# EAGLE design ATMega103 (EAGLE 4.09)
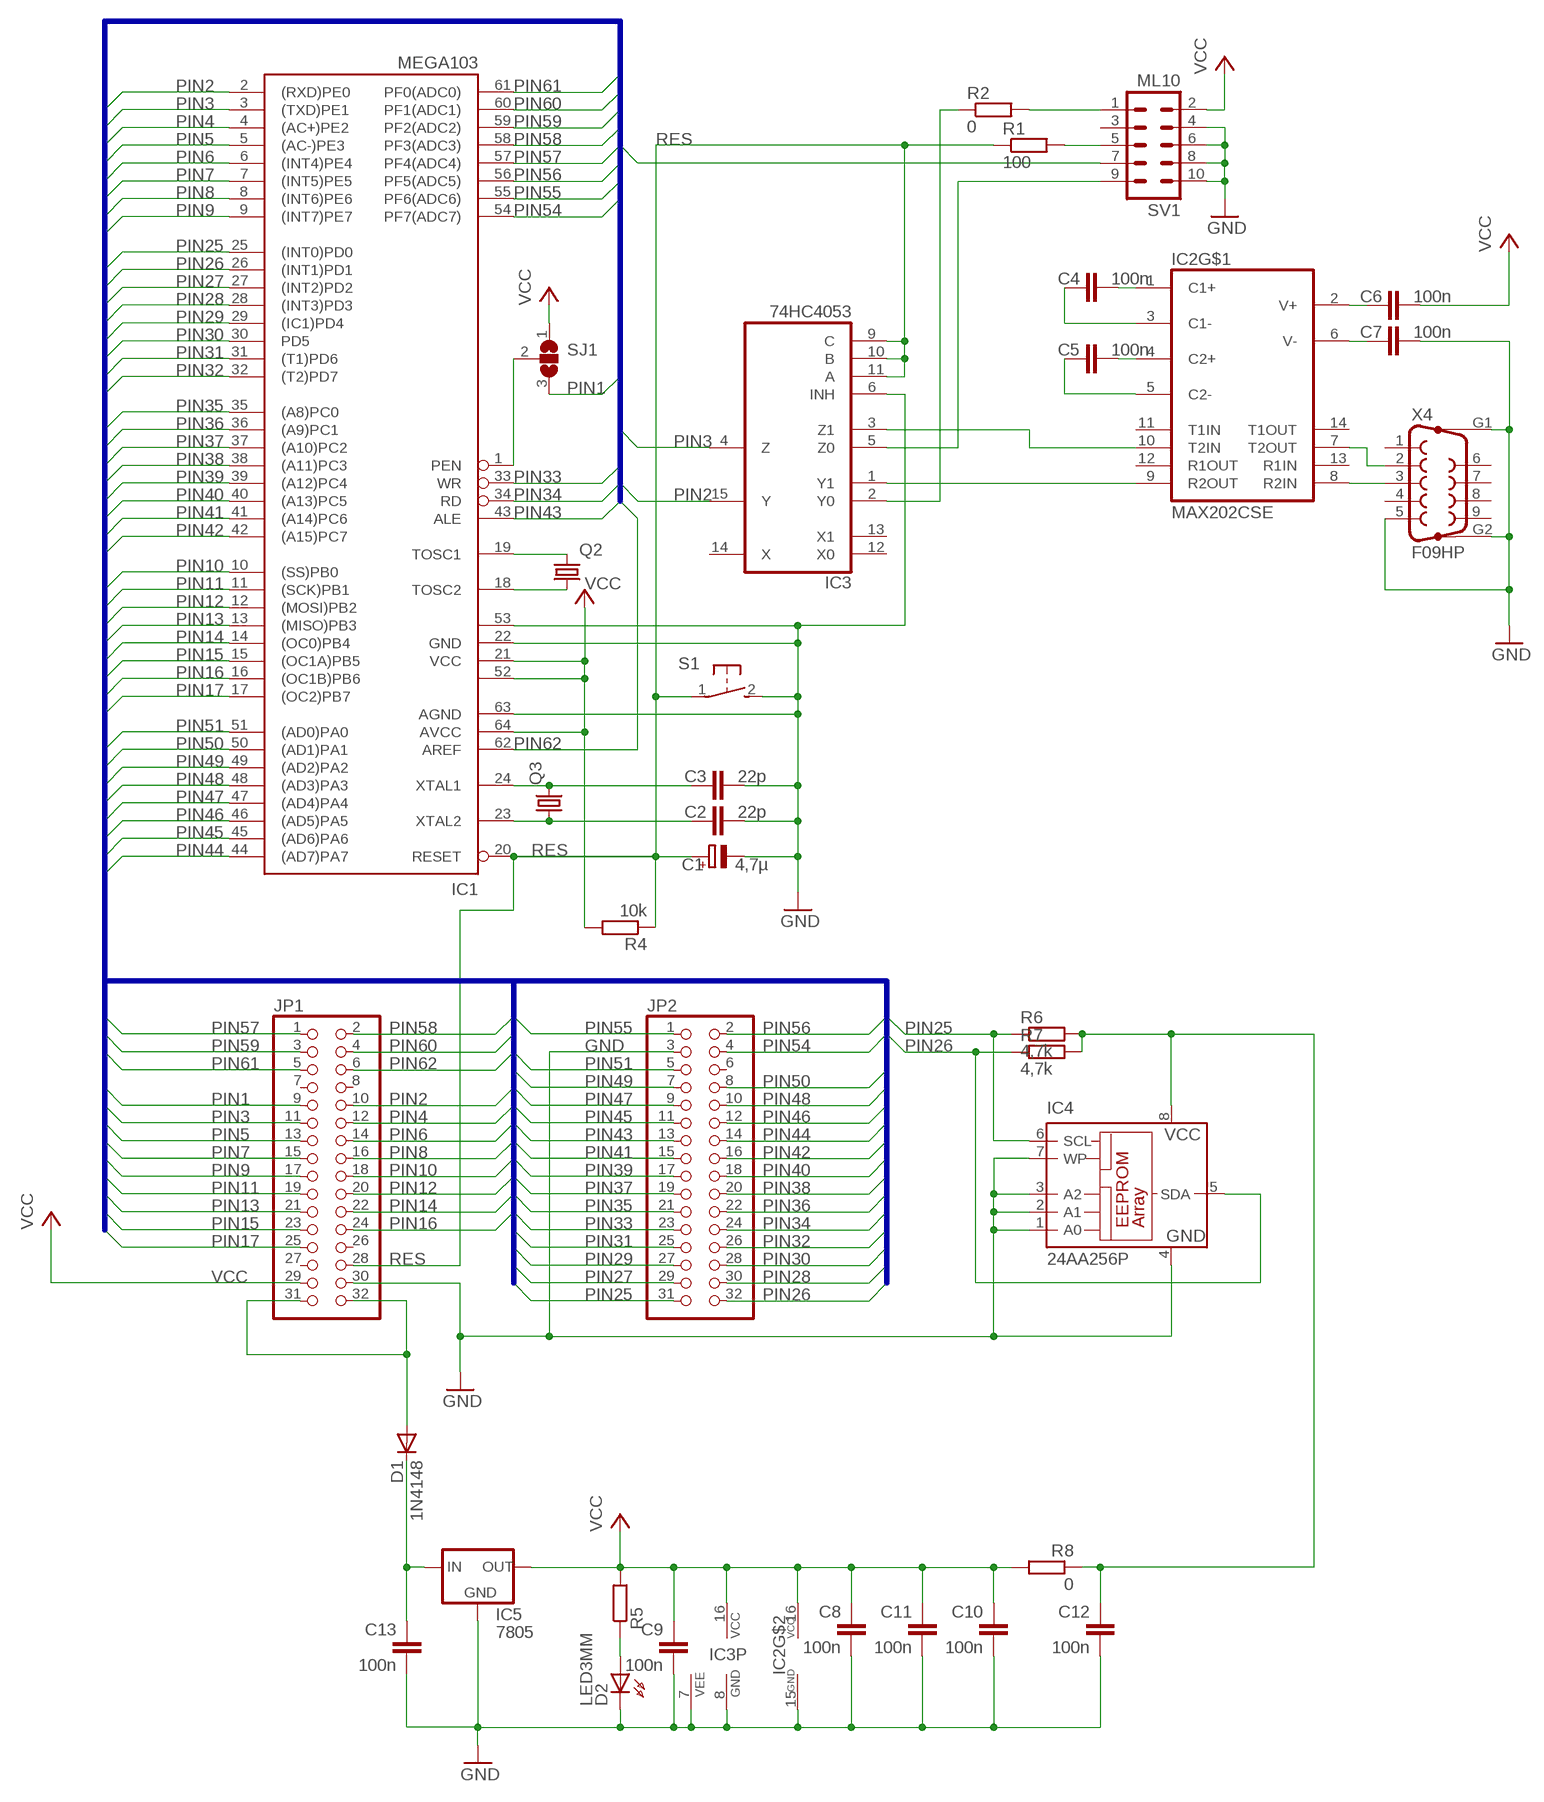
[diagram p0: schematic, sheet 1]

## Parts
C1  4,7µ  CPOL-EUE2-5  [E2-5]
C2  22p  C-EUC3216  [C3216]
C3  22p  C-EUC3216  [C3216]
C4  100n  C-EUC3216  [C3216]
C5  100n  C-EUC3216  [C3216]
C6  100n  C-EUC3216  [C3216]
C7  100n  C-EUC3216  [C3216]
C8  100n  C-EUC3216  [C3216]
C9  100n  C-EUC3216  [C3216]
C10  100n  C-EUC3216  [C3216]
C11  100n  C-EUC3216  [C3216]
C12  100n  C-EUC1206  [C1206]
C13  100n  C-EUC1206  [C1206]
D1  1N4148  DIODE-SOD106-R  [SOD106-R]
D2  LED3MM  [LED3MM]
IC1  MEGA103  [TQFP64]
IC2  MAX202CSE  [SO16]
IC3  74HC4053  4053D  [SO16]
IC4  24AA256P  [DIL8]
IC5  7805  78XXL  [78XXL]
JP1  PINHD-2X16  [2X16]
JP2  PINHD-2X16  [2X16]
Q2  TC26H  [TC26H]
Q3  HC49/S  [HC49/S]
R1  100  R-EU_R3216  [R3216]
R2  0  R-EU_R3216  [R3216]
R4  10k  R-EU_R3216  [R3216]
R5  R-EU_R3216  [R3216]
R6  4,7k  R-EU_M3216  [M3216]
R7  4,7k  R-EU_M3216  [M3216]
R8  0  R-EU_R3216  [R3216]
S1  31-XX  [B3F-31XX]
SJ1  SJ2W  [SJ_2]
SV1  ML10  [ML10]
X4  F09HP  [F09HP]

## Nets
GND: C1.- C2.2 C3.2 C7.2 C8.2 C9.2 C10.2 C11.2 C12.2 C13.2 D2.K(C) IC1.22(GND) IC1.53(GND1) IC1.63(AGND) IC2.15(GND) IC3.6(INH) IC3.7(VEE) IC3.8(GND) IC4.1(A0) IC4.2(A1) IC4.3(A2) IC4.4(GND) IC4.7(WP) IC5.GND JP1.30 JP2.3 S1.2(S) SV1.4 SV1.6 SV1.8 SV1.10 X4.5 X4.G1 X4.G2
N$1: C3.1 IC1.24(XTAL1) Q3.2
N$2: C2.1 IC1.23(XTAL2) Q3.1
N$3: IC1.19(TOSC1) Q2.1
N$4: IC1.18(TOSC2) Q2.2
N$9: D2.A R5.1
N$10: R2.2 SV1.1
N$11: D1.A JP1.31 JP1.32
N$12: IC1.1(PEN) SJ1.2
N$13: C12.1 IC4.8(VCC) R6.2 R7.2 R8.1
N$14: IC2.9(R2OUT) IC3.1(Y1)
N$16: IC3.5(Z0) SV1.9
N$17: IC3.2(Y0) R2.1
N$18: IC2.10(T2IN) IC3.3(Z1)
N$19: C4.2 IC2.1(C1+)
N$20: C5.2 IC2.4(C2+)
N$21: C5.1 IC2.5(C2-)
N$22: C6.1 IC2.2(V+)
N$23: C7.1 IC2.6(V-)
N$24: IC2.7(T2OUT) X4.2
N$25: IC2.8(R2IN) X4.3
N$26: C13.1 D1.C IC5.IN
N$28: R1.2 SV1.5
N$29: C4.1 IC2.3(C1-)
PIN1: JP1.9 SJ1.3
PIN2: IC1.2((RXD)PE0) IC3.15(Y) JP1.10
PIN3: IC1.3((TXD)PE1) IC3.4(Z) JP1.11
PIN4: IC1.4((AC+)PE2) JP1.12
PIN5: IC1.5((AC-)PE3) JP1.13
PIN6: IC1.6((INT4)PE4) JP1.14
PIN7: IC1.7((INT5)PE5) JP1.15
PIN8: IC1.8((INT6)PE6) JP1.16
PIN9: IC1.9((INT7)PE7) JP1.17
PIN10: IC1.10((SS)PB0) JP1.18
PIN11: IC1.11((SCK)PB1) JP1.19 SV1.7
PIN12: IC1.12((MOSI)PB2) JP1.20
PIN13: IC1.13((MISO)PB3) JP1.21
PIN14: IC1.14((OC0)PB4) JP1.22
PIN15: IC1.15((OC1A)PB5) JP1.23
PIN16: IC1.16((OC1B)PB6) JP1.24
PIN17: IC1.17((OC2)PB7) JP1.25
PIN25: IC1.25((INT0)PD0) IC4.6(SCL) JP2.31 R6.1
PIN26: IC1.26((INT1)PD1) IC4.5(SDA) JP2.32 R7.1
PIN27: IC1.27((INT2)PD2) JP2.29
PIN28: IC1.28((INT3)PD3) JP2.30
PIN29: IC1.29((IC1)PD4) JP2.27
PIN30: IC1.30(PD5) JP2.28
PIN31: IC1.31((T1)PD6) JP2.25
PIN32: IC1.32((T2)PD7) JP2.26
PIN33: IC1.33(WR) JP2.23
PIN34: IC1.34(RD) JP2.24
PIN35: IC1.35((A8)PC0) JP2.21
PIN36: IC1.36((A9)PC1) JP2.22
PIN37: IC1.37((A10)PC2) JP2.19
PIN38: IC1.38((A11)PC3) JP2.20
PIN39: IC1.39((A12)PC4) JP2.17
PIN40: IC1.40((A13)PC5) JP2.18
PIN41: IC1.41((A14)PC6) JP2.15
PIN42: IC1.42((A15)PC7) JP2.16
PIN43: IC1.43(ALE) JP2.13
PIN44: IC1.44((AD7)PA7) JP2.14
PIN45: IC1.45((AD6)PA6) JP2.11
PIN46: IC1.46((AD5)PA5) JP2.12
PIN47: IC1.47((AD4)PA4) JP2.9
PIN48: IC1.48((AD3)PA3) JP2.10
PIN49: IC1.49((AD2)PA2) JP2.7
PIN50: IC1.50((AD1)PA1) JP2.8
PIN51: IC1.51((AD0)PA0) JP2.5
PIN54: IC1.54(PF7(ADC7)) JP2.4
PIN55: IC1.55(PF6(ADC6)) JP2.1
PIN56: IC1.56(PF5(ADC5)) JP2.2
PIN57: IC1.57(PF4(ADC4)) JP1.1
PIN58: IC1.58(PF3(ADC3)) JP1.2
PIN59: IC1.59(PF2(ADC2)) JP1.3
PIN60: IC1.60(PF1(ADC1)) JP1.4
PIN61: IC1.61(PF0(ADC0)) JP1.5
PIN62: IC1.62(AREF) JP1.6
RES: C1.+ IC1.20(RESET) IC3.9(C) IC3.10(B) IC3.11(A) JP1.28 R1.1 R4.1 S1.1(P)
VCC: C6.2 C8.1 C9.1 C10.1 C11.1 IC1.21(VCC) IC1.52(VCC1) IC1.64(AVCC) IC2.16(VCC) IC3.16(VCC) IC5.OUT JP1.29 R4.2 R5.2 R8.2 SJ1.1 SV1.2
Unconnected: IC2.11(T1IN) IC2.12(R1OUT) IC2.13(R1IN) IC2.14(T1OUT) IC3.12(X0) IC3.13(X1) IC3.14(X) JP1.7 JP1.8 JP1.26 JP1.27 JP2.6 SV1.3 X4.1 X4.4 X4.6 X4.7 X4.8 X4.9

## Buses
PIN[1..64]

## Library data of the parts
C1 = rcl:CPOL-EU: POLARIZED CAPACITOR, European symbol
C2-C13 = rcl:C-EU: CAPACITOR, European symbol
D1 = diode:DIODE-: DIODE
D2 = led:LED3MM: LED
IC1 = atmel:MEGA103*: MICROCONTROLLER Low-voltage (L) 128 Kbytes FLASH 4 Kbytes SRAM 2 Kbytes EEPROM UART RTC 8-channel 10 bit ADC
IC2 = maxim:MAX202CSE
IC3 = 40xx:4053: Triple 2-channel ANALOG MULTIPLEXER
IC4 = microchip:24*: Serial EEPROM I2C
IC5 = v-reg:78XXL: VOLTAGE REGULATOR
JP1 JP2 = pinhead:PINHD-2X16: PIN HEADER
Q2 = crystal:TC26H: CRYSTAL
Q3 = crystal:HC49/S: CRYSTAL
R1 R2 R4-R8 = rcl:R-EU_: RESISTOR, European symbol
S1 = switch-omron:31-XX: OMRON SWITCH
SJ1 = jumper:SJ2W: SMD solder JUMPER
SV1 = CON-ML:ML10
X4 = SUBD-A:F09HP

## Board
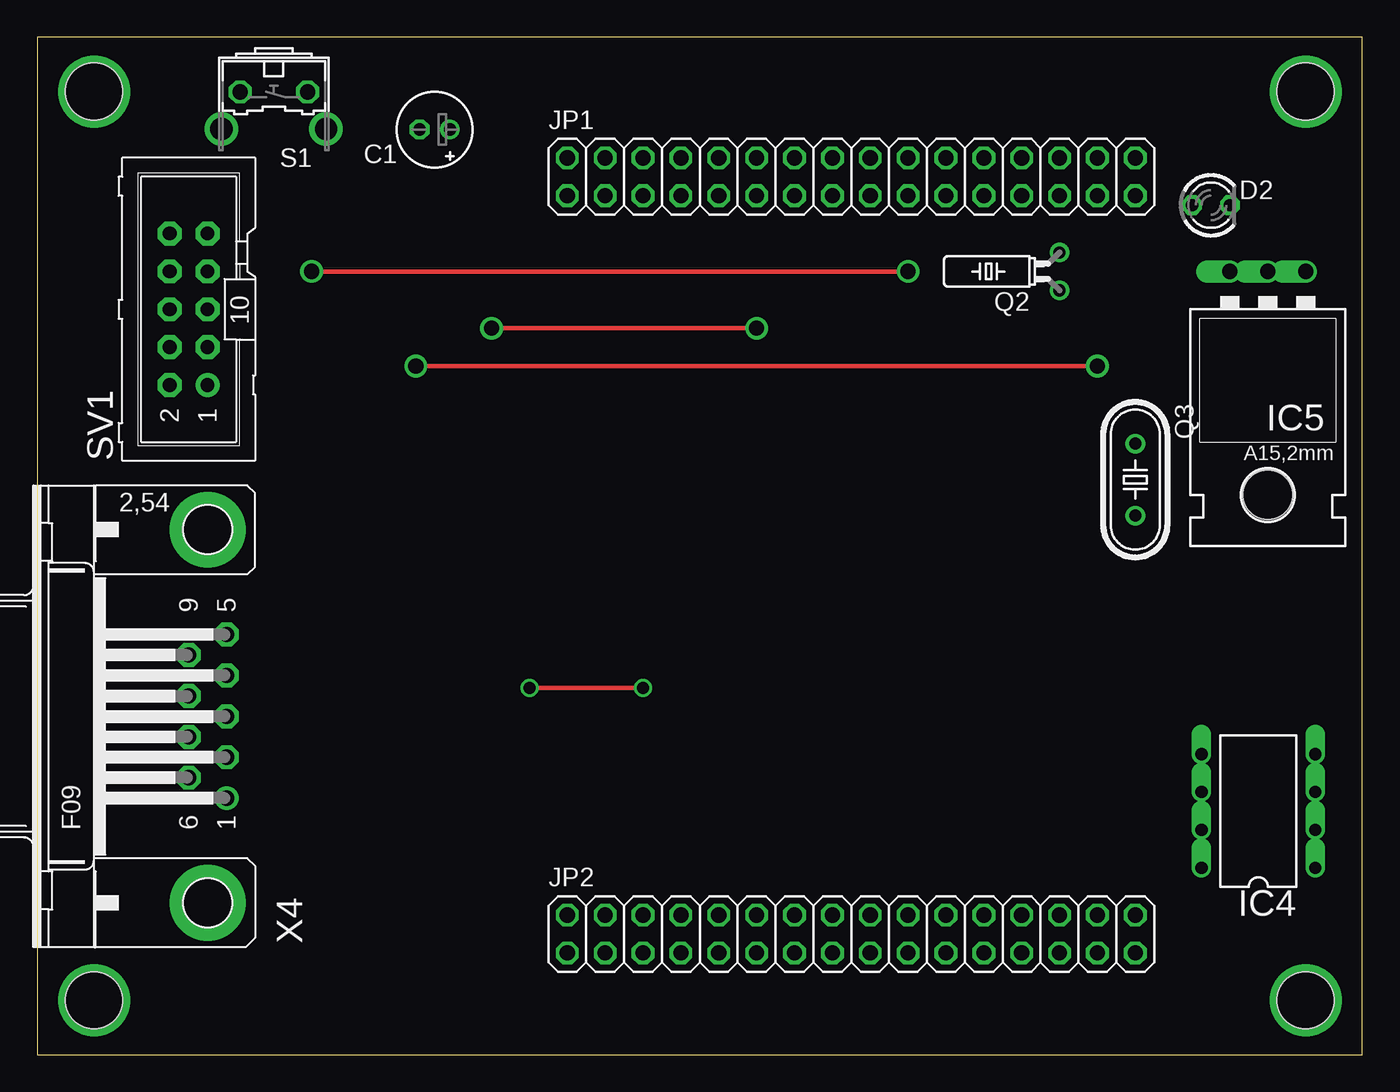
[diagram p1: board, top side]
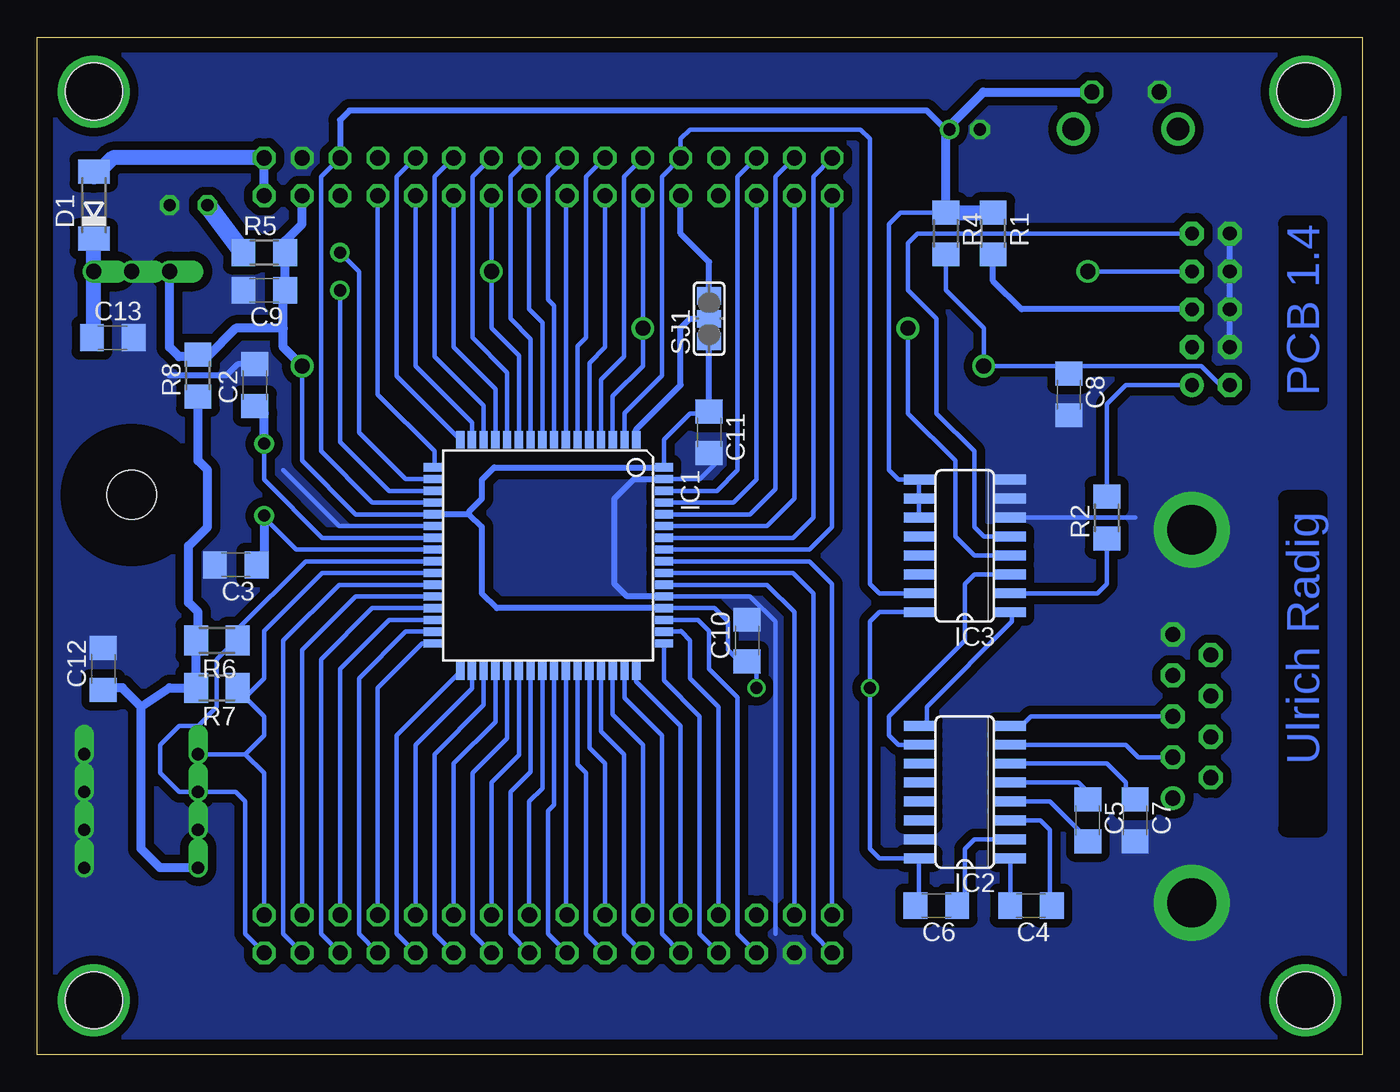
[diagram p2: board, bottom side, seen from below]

Size 88.88 x 68.25 mm. Coordinates in mm from the lower left corner, seen from the top.
Outline: 0,0 88.88,0 88.88,68.25 0,68.25 0,0
Copper layers used: Top, Bottom
Holes 3.81 mm at 3.8,64.6 3.8,3.64 85.08,3.64 85.08,64.6

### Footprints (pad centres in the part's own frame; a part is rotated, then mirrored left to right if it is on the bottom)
E2-5 = drill 0.813 pad 1.27 round: + -1.016,0 | drill 0.813 pad 1.27 octagon: - 1.016,0
C3216 = smd 1.6 x 1.8: 1 -1.4,0; 2 1.4,0
C1206 = smd 1.6 x 1.8: 1 -1.4,0; 2 1.4,0
SOD106-R = smd 1.6 x 2.1: A 2.25,0; C -2.25,0
LED3MM = drill 0.813 octagon: A -1.27,0; K 1.27,0
TQFP64 = smd 1.194 x 0.559: 1 -7.76,5.905; 2 -7.76,5.118; 3 -7.76,4.331; 4 -7.76,3.543; 5 -7.76,2.756; 6 -7.76,1.968; 7 -7.76,1.181; 8 -7.76,0.394; 9 -7.76,-0.394; 10 -7.76,-1.181; 11 -7.76,-1.968; 12 -7.76,-2.756; 13 -7.76,-3.543; 14 -7.76,-4.331; 15 -7.76,-5.118; 16 -7.76,-5.905; 33 7.76,-5.905; 34 7.76,-5.118; 35 7.76,-4.331; 36 7.76,-3.543; 37 7.76,-2.756; 38 7.76,-1.968; 39 7.76,-1.181; 40 7.76,-0.394; 41 7.76,0.394; 42 7.76,1.181; 43 7.76,1.968; 44 7.76,2.756; 45 7.76,3.543; 46 7.76,4.331; 47 7.76,5.118; 48 7.76,5.905 | smd 0.559 x 1.194: 17 -5.905,-7.76; 18 -5.118,-7.76; 19 -4.331,-7.76; 20 -3.543,-7.76; 21 -2.756,-7.76; 22 -1.968,-7.76; 23 -1.181,-7.76; 24 -0.394,-7.76; 25 0.394,-7.76; 26 1.181,-7.76; 27 1.968,-7.76; 28 2.756,-7.76; 29 3.543,-7.76; 30 4.331,-7.76; 31 5.118,-7.76; 32 5.905,-7.76; 49 5.905,7.76; 50 5.118,7.76; 51 4.331,7.76; 52 3.543,7.76; 53 2.756,7.76; 54 1.968,7.76; 55 1.181,7.76; 56 0.394,7.76; 57 -0.394,7.76; 58 -1.181,7.76; 59 -1.968,7.76; 60 -2.756,7.76; 61 -3.543,7.76; 62 -4.331,7.76; 63 -5.118,7.76; 64 -5.905,7.76
SO16 = smd 0.66 x 2.032: 1 -4.445,-3.073; 2 -3.175,-3.073; 3 -1.905,-3.073; 4 -0.635,-3.073; 5 0.635,-3.073; 6 1.905,-3.073; 7 3.175,-3.073; 8 4.445,-3.073; 9 4.445,3.073; 10 3.175,3.073; 11 1.905,3.073; 12 0.635,3.073; 13 -0.635,3.073; 14 -1.905,3.073; 15 -3.175,3.073; 16 -4.445,3.073
DIL8 = drill 0.813 offset: 1 -3.81,-3.81; 2 -1.27,-3.81; 3 1.27,-3.81; 4 3.81,-3.81; 5 3.81,3.81; 6 1.27,3.81; 7 -1.27,3.81; 8 -3.81,3.81
78XXL = drill 1.016 offset: GND 0,-3.81; IN -2.54,-3.81; OUT 2.54,-3.81 | hole 3.302: 0,11.176
2X16 = drill 1.016 octagon: 1 -19.05,-1.27; 2 -19.05,1.27; 3 -16.51,-1.27; 4 -16.51,1.27; 5 -13.97,-1.27; 6 -13.97,1.27; 7 -11.43,-1.27; 8 -11.43,1.27; 9 -8.89,-1.27; 10 -8.89,1.27; 11 -6.35,-1.27; 12 -6.35,1.27; 13 -3.81,-1.27; 14 -3.81,1.27; 15 -1.27,-1.27; 16 -1.27,1.27; 17 1.27,-1.27; 18 1.27,1.27; 19 3.81,-1.27; 20 3.81,1.27; 21 6.35,-1.27; 22 6.35,1.27; 23 8.89,-1.27; 24 8.89,1.27; 25 11.43,-1.27; 26 11.43,1.27; 27 13.97,-1.27; 28 13.97,1.27; 29 16.51,-1.27; 30 16.51,1.27; 31 19.05,-1.27; 32 19.05,1.27
TC26H = drill 0.813 round: 1 -1.27,0; 2 1.27,0
HC49/S = drill 0.813 round: 1 -2.413,0; 2 2.413,0
R3216 = smd 1.6 x 1.8: 1 -1.4,0; 2 1.4,0
M3216 = smd 1.6 x 2: 1 -1.4,0; 2 1.4,0
B3F-31XX = drill 1.016 octagon: 1 -2.261,-1.245; 2 2.261,-1.245 | drill 1.499 pad 2.159 round: 3 -3.505,1.245; 4 3.505,1.245
SJ_2 = smd 1.168 x 1.6: 1 -1.524,0; 2 0,0; 3 1.524,0
ML10 = drill 0.914 pad 1.6 round: 1 -5.08,-1.27 | drill 0.914 pad 1.6 octagon: 2 -5.08,1.27; 3 -2.54,-1.27; 4 -2.54,1.27; 5 0,-1.27; 6 0,1.27; 7 2.54,-1.27; 8 2.54,1.27; 9 5.08,-1.27; 10 5.08,1.27
F09HP = drill 1.016 pad 1.6 round: 1 -5.486,-1.27 | drill 1.016 pad 1.6 octagon: 2 -2.743,-1.27; 3 0,-1.27; 4 2.743,-1.27; 5 5.486,-1.27; 6 -4.115,1.27; 7 -1.372,1.27; 8 1.372,1.27; 9 4.115,1.27 | drill 3.302 pad 5.08 round: G1 -12.522,0; G2 12.522,0

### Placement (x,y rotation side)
C1  26.66,62.07 180 top
C2  74.29,44.92 90 bottom
C3  75.56,32.85 180 bottom
C4  22.22,10 180 bottom
C5  18.41,15.71 270 bottom
C6  28.57,10 180 bottom
C7  15.24,15.71 270 bottom
C8  19.68,44.28 270 bottom
C9  73.66,51.27 180 bottom
C10  41.27,27.77 90 bottom
C11  43.81,41.74 270 bottom
C12  84.45,25.87 90 bottom
C13  83.81,48.1 0 bottom
D1  85.08,56.99 90 bottom
D2  78.73,56.99 0 top
IC1  54.61,33.49 270 bottom
IC2  26.66,17.62 90 bottom
IC3  26.66,34.12 90 bottom
IC4  81.91,16.34 90 top
IC5  82.55,48.73 180 top
JP1  54.61,58.89 0 top
JP2  54.61,8.09 0 top
Q2  68.57,52.54 90 top
Q3  73.66,38.57 270 top
R1  24.76,55.08 270 bottom
R2  17.14,36.03 90 bottom
R4  27.93,55.08 270 bottom
R5  73.66,53.81 0 bottom
R6  76.83,27.77 180 bottom
R7  76.83,24.6 180 bottom
R8  78.1,45.55 90 bottom
S1  15.87,63.34 180 top
SJ1  43.81,49.37 90 bottom
SV1  10.16,50 90 top
X4  11.43,22.7 90 top

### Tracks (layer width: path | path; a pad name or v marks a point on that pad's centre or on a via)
GND
  Bottom 0.305: IC1.22 68.64,35.46 72.38,39.2 | IC1.53 41.05,30.73 39.37,29.05 39.37,8.09 | IC1.63 44.41,38.61 43.18,39.84 | 15.24,36.03 IC3.6
  Bottom 0.406: SV1.10 SV1.8 SV1.6 SV1.4 | IC1.63 48.85,38.61 50.16,37.3 50.16,31.59 49.31,30.73 IC1.53 | C2.2 75.43,46.32 76.19,45.55 80,45.55
  pour Bottom (isolate 0.571, no thermals): 0.63,67.78 0.63,1.11 87.62,1.11 87.62,67.15 0.63,67.15
N$1
  Bottom 0.305: IC1.24 71.51,33.88 73.66,36.03
  Bottom 0.406: 74.16,32.98 C3.1 | 73.66,36.03 Q3.2
  Bottom 0.61: 73.66,36.03 73.66,32.85 73.78,32.98 74.16,32.98
N$2
  Bottom 0.305: IC1.23 69.76,34.67 73.66,38.57 Q3.1 73.66,41.11 | C2.1 74.29,43.65 73.66,43.02
  Bottom 0.61: Q3.1 73.66,43.02
N$3
  Bottom 0.305: IC1.19 65.29,37.82 68.57,41.11 Q2.1
N$4
  Bottom 0.305: IC1.18 64.17,38.61 67.3,41.74 67.3,52.54 Q2.2
N$5  (via drill 3.81)
  other vias: 3.8,64.6
N$6  (via drill 3.81)
  other vias: 85.08,64.6
N$7  (via drill 3.81)
  other vias: 85.08,3.64
N$8  (via drill 3.81)
  other vias: 3.8,3.64
N$9
  Bottom 1.27: R5.1 D2.A
N$10
  Bottom 0.305: SV1.1 15.87,44.92 17.14,43.65 R2.2 17.14,37.3
N$11
  Bottom 0.61: JP1.31 JP1.32 | 85.08,58.89 D1.A
  Bottom 1.016: JP1.32 83.81,60.16 85.08,58.89
N$12
  Bottom 0.406: SJ1.2 45.08,49.37 45.72,48.73 45.72,44.92 48.7,41.94 IC1.1
N$13
  Bottom 0.406: 84.45,23.96 C12.1 84.45,24.6
  Bottom 0.61: R8.1 78.1,39.84 77.46,39.2 77.46,35.4 78.73,34.12 78.73,30.31 78.1,29.68 78.1,27.77 R6.2 78.23,24.09 78.1,24.6 | 78.1,24.6 R7.2 | IC4.8 80.64,12.54 81.91,13.8 81.91,23.33 | 81.91,23.33 80,24.6 78.1,24.6 | 84.45,24.6 83.18,24.6 81.91,23.33
N$14
  Bottom 0.305: IC3.1 23.49,29.68 23.49,29.05 29.2,23.33 29.2,22.06 IC2.9 29.84,22.06
N$16
  Bottom 0.305: SV1.9 29.84,55.08 30.47,54.45 30.47,51.27 28.57,49.37 28.57,43.02 26.03,40.48 26.03,35.4 25.39,34.76 IC3.5 23.49,34.76
N$17
  Bottom 0.305: IC3.2 17.77,30.95 17.14,31.59 R2.1
N$18
  Bottom 0.305: IC3.3 26.03,32.22 26.66,31.59 26.66,27.77 31.74,22.7 31.74,21.42 31.11,20.79 IC2.10
N$19
  Bottom 0.305: C4.2 23.49,10 23.59,10.1 IC2.1
N$20
  Bottom 0.305: IC2.4 20.95,16.98 18.41,14.44 C5.2
N$21
  Bottom 0.305: C5.1 18.41,17.62 19.04,18.25 IC2.5
N$22
  Bottom 0.305: IC2.2 26.03,14.44 26.66,13.8 26.66,10.63 27.3,10 C6.1
N$23
  Bottom 0.305: C7.1 15.87,17.11 | 15.87,17.11 15.87,16.98 | 15.87,17.11 15.87,18.25 17.14,19.52 IC2.6
N$24
  Bottom 0.305: X4.2 15.03,19.95 15.87,20.79 IC2.7
N$25
  Bottom 0.305: IC2.8 22.86,22.06 22.22,22.7 X4.3
N$26
  Bottom 0.61: C13.1 85.08,48.1
  Bottom 1.016: 85.08,48.1 IC5.IN D1.C
N$28
  Bottom 0.406: SV1.5 22.86,50 24.76,51.9 R1.2
N$29
  Bottom 0.305: IC2.3 21.58,15.71 20.95,15.08 20.95,10 C4.1
PIN1
  Bottom 0.406: SJ1.3 43.81,53.18 45.72,55.08 JP1.9
PIN2
  Bottom 0.305: IC1.2 49.49,43.05 46.98,45.55 46.98,58.89 JP1.10 45.72,61.43 45.08,62.07 33.65,62.07 33.02,61.43 33.02,49.37 33.02,48.73 33.02,46.82 33.02,31.59 32.38,30.95 29.84,30.95 | IC3.15 29.2,30.95 | IC3.15 29.84,30.95 | IC3.15 29.84,30.95
PIN3  (via drill 1.02)
  Top 0.305: v30.47,48.73 v48.26,48.73
  Bottom 0.305: IC1.3 50.27,44.17 48.26,46.19 v48.26,48.73 JP1.11 | v30.47,48.73 30.47,43.02 27.3,39.84 27.3,34.76 26.03,33.49 IC3.4
PIN4
  Bottom 0.305: IC1.4 51.06,45.29 49.53,46.82 49.53,58.89 JP1.12
PIN5
  Bottom 0.305: IC1.5 51.85,46.41 50.8,47.46 JP1.13
PIN6
  Bottom 0.305: IC1.6 52.64,47.52 52.07,48.1 52.07,58.89 JP1.14
PIN7
  Bottom 0.305: IC1.7 53.42,57.53
  Bottom 0.406: 53.42,57.53 JP1.15
PIN8
  Bottom 0.305: IC1.8 54.21,50.24 54.61,50.63 54.61,58.89 JP1.16
PIN9
  Bottom 0.305: IC1.9 55,49.12 55.88,50 JP1.17
PIN10
  Bottom 0.305: IC1.10 55.79,48.01 57.15,49.37 57.15,58.89 JP1.18
PIN11  (via drill 1.02)
  Top 0.305: v18.41,52.54 v58.41,52.54
  Bottom 0.305: IC1.11 56.57,46.89 58.41,48.73 v58.41,52.54 JP1.19 | SV1.7 v18.41,52.54
PIN12
  Bottom 0.305: IC1.12 57.36,45.77 59.69,48.1 59.69,58.89 JP1.20
PIN13
  Bottom 0.305: IC1.13 58.15,44.65 60.96,47.46 JP1.21
PIN14
  Bottom 0.305: JP1.22 62.23,58.89 62.23,46.82 58.94,43.54 IC1.14
PIN15
  Bottom 0.305: IC1.15 59.72,42.42 63.5,46.19 JP1.23
PIN16
  Bottom 0.305: IC1.16 64.77,45.5 64.77,58.89 JP1.24
PIN17
  Bottom 0.305: IC1.17 62.23,39.4 62.23,40.48 66.03,44.28 JP1.25
PIN25
  Bottom 0.305: JP2.31 74.92,8.09 74.92,16.98 75.56,17.62 IC4.6 79.37,17.62 80.64,18.88 80.64,20.79 79.37,22.06 78.1,22.06 76.83,23.33 76.83,26.51 75.56,27.77 R6.1 75.43,28.54 70.87,33.1 IC1.25
PIN26
  Bottom 0.305: JP2.32 73.66,18.88 74.92,20.16 | IC1.26 69.76,32.31 73.66,28.41 73.66,25.23 74.92,23.96 | 75.56,23.96 R7.1 74.92,23.96 | 74.92,20.16 73.66,21.42 73.66,22.7 74.92,23.96 | 74.92,20.16 IC4.5
PIN27
  Bottom 0.305: IC1.27 68.64,31.52 72.38,27.77 72.38,8.09 JP2.29
PIN28
  Bottom 0.305: IC1.28 67.52,30.73 71.11,27.14 JP2.30
PIN29
  Bottom 0.305: JP2.27 69.84,8.09 69.84,26.51 66.4,29.95 IC1.29
PIN30
  Bottom 0.305: IC1.30 65.29,29.16 68.57,25.87 JP2.28
PIN31
  Bottom 0.305: JP2.25 67.3,8.09 67.3,25.23 64.17,28.37 IC1.31
PIN32
  Bottom 0.305: JP2.26 66.03,24.6 63.05,27.58 IC1.32
PIN33
  Bottom 0.305: IC1.33 60.51,25.68 64.77,21.42 64.77,8.09 JP2.23
PIN34
  Bottom 0.305: IC1.34 59.72,24.56 63.5,20.79 JP2.24
PIN35
  Bottom 0.305: IC1.35 58.94,23.44 62.23,20.16 62.23,8.09 JP2.21
PIN36
  Bottom 0.305: IC1.36 58.15,22.33 60.96,19.52 JP2.22
PIN37
  Bottom 0.305: IC1.37 57.36,21.21 59.69,18.88 59.69,8.09 JP2.19
PIN38
  Bottom 0.305: IC1.38 56.57,20.09 58.41,18.25 JP2.20
PIN39
  Bottom 0.305: IC1.39 55.79,18.97 57.15,17.62 57.15,8.09 JP2.17
PIN40
  Bottom 0.305: IC1.40 55,17.86 55.88,16.98 JP2.18
PIN41
  Bottom 0.305: IC1.41 54.21,16.74 54.61,16.34 54.61,8.09 JP2.15
PIN42
  Bottom 0.305: IC1.42 53.42,9.45 JP2.16
PIN43
  Bottom 0.305: IC1.43 52.64,19.46 52.07,18.88 52.07,8.09 JP2.13
PIN44
  Bottom 0.305: IC1.44 51.85,20.57 50.8,19.52 JP2.14
PIN45
  Bottom 0.305: IC1.45 51.06,21.69 49.53,20.16 49.53,8.09 JP2.11
PIN46
  Bottom 0.305: IC1.46 50.27,22.81 48.26,20.79 JP2.12
PIN47
  Bottom 0.305: IC1.47 49.49,23.93 46.98,21.42 46.98,8.09 JP2.9
PIN48
  Bottom 0.305: IC1.48 48.7,25.04 45.72,22.06 JP2.10
PIN49
  Bottom 0.305: JP2.7 44.45,8.09 44.45,22.7 46.85,25.09 IC1.49
PIN50
  Bottom 0.305: 45.68,28.37 IC1.50 | JP2.8 43.18,23.33 45.08,25.23 45.08,27.77 45.68,28.37 | 45.68,28.37 45.72,28.41
PIN51
  Bottom 0.305: JP2.5 41.91,8.09 41.91,23.96 43.81,25.87 43.81,28.41 44.56,29.16 IC1.51
PIN54
  Bottom 0.305: IC1.54 39.94,31.52 38.1,29.68 JP2.4
PIN55
  Bottom 0.305: JP2.1 36.83,8.09 36.83,30.95 38.18,32.31 IC1.55
PIN56
  Bottom 0.305: IC1.56 37.07,33.1 35.55,31.59 JP2.2
PIN57
  Bottom 0.305: IC1.57 37.07,33.88 35.55,35.4 JP1.1
PIN58
  Bottom 0.305: JP1.2 36.83,58.89 36.83,36.03 38.18,34.67 IC1.58
PIN59
  Bottom 0.305: IC1.59 39.94,35.46 38.1,37.3 JP1.3
PIN60
  Bottom 0.305: JP1.4 39.37,58.89 39.37,37.94 41.05,36.25 IC1.60
PIN61
  Bottom 0.305: IC1.61 42.17,37.03 40.64,38.57 JP1.5
PIN62
  Bottom 0.305: JP1.6 41.91,58.89 41.91,39.2 43.29,37.82 IC1.62
RES
  Bottom 0.305: JP1.28 69.84,58.89 69.84,40.48 66.4,37.03 IC1.20 | R4.1 30.98,56.48 31.74,55.71 31.74,39.2 31.11,38.57 IC3.9 29.74,37.4 29.84,37.3 IC3.10 29.74,36.13 29.84,36.03 IC3.11
  Bottom 0.406: 27.93,62.07 29.2,63.34 67.94,63.34 68.57,62.7 JP1.28 | R1.1 25.39,56.35 25.52,56.48
  Bottom 0.61: R4.1 27.93,62.07 | 27.93,62.07 C1.+ | S1.1 25.42,64.58 27.93,62.07
  Bottom 1.016: R4.1 25.52,56.48
VCC  (via drill 0.81, 1.02)
  Top 0.305: v71.11,46.19 v25.39,46.19 | v33.02,24.6 v40.64,24.6
  Bottom 0.305: v71.11,46.19 71.11,39.84 67.52,36.25 IC1.21 | 19.68,46.19 v25.39,46.19 25.39,48.73 27.93,51.27 R4.2 | 72.38,51.27 C9.1 | 72.25,53.68 72.38,53.81 R5.2 72.25,54.57 | 41.78,26.38 42.54,27.14 42.54,29.05 43.44,29.95 IC1.52 | IC1.64 46.85,41.25 45.08,43.02 43.81,43.02 C11.1 | 59.9,36.25 59.9,36.45 | C6.2 29.84,10 29.74,10.1 IC2.16 32.38,13.17 33.02,13.8 v33.02,24.6 33.02,29.05 32.38,29.68 IC3.16 | 19.68,46.19 C8.1 | SV1.2 9.52,44.92 10.79,46.19 19.68,46.19 | v40.64,24.6 40.64,25.87 41.27,26.51
  Bottom 0.406: IC1.52 58.05,29.95 59.05,30.95 59.05,35.4 59.9,36.25 IC1.21 | 59.9,36.45 59.05,37.3 59.05,38.57 58.22,39.4 IC1.64 | C10.1 41.27,26.51 41.4,26.38 41.78,26.38 | 43.81,48.1 SJ1.1 C11.1 | 78.1,46.82 R8.2
  Bottom 0.61: v71.11,46.19 72.38,47.46 72.38,48.73 | 72.38,48.73 72.38,51.27 | C9.1 72.25,53.68 | 72.25,54.57 71.11,55.71 JP1.29 | 72.38,48.73 75.56,48.73 77.46,46.82 78.1,46.82 78.73,46.82 79.37,46.82 80,47.46 IC5.OUT

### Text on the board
Bottom: PCB 1.4 | Ulrich Radig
